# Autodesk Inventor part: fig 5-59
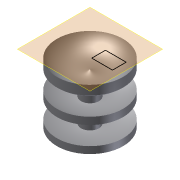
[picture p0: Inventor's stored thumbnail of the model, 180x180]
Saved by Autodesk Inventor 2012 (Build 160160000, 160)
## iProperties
Created: 2004-05
Part Number: fig 5-59
Document SubType Name: Modeling
Designer: CADCIM Technologies
Manufacturer: Standard
Standards Organization: Custom
Density: 1 g/cm^3
Material: Default
Author: CADCIM Technologies
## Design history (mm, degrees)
sketch "Sketch1"
  geometry: L1 (0.098, 22.743)-(0.098, 0.516); L2 (-3.621, 19.305)-(-3.621, 13.061); L3 (-3.621, 10.379)-(-3.621, 3.25); L4 (-3.664, 0.516)-(0.098, 0.516); L5 (-13.694, 4.7)-(-13.694, 1.836); L6 (-13.694, 26.851)-(-13.694, 23.014); L7 (-13.694, 15.335)-(-13.694, 12.343); A1 r 10.546 centre (-4.597, 32.185) between (-13.694, 26.851) and (0.098, 22.743); A2 r 21.828 centre (-4.597, 32.185) between (-13.694, 12.343) and (-3.621, 10.379); A3 r 12.918 centre (-4.597, 32.185) between (-13.694, 23.014) and (-3.621, 19.305); A4 r 19.149 centre (-4.597, 32.185) between (-13.694, 15.335) and (-3.621, 13.061); A5 r 28.952 centre (-4.597, 32.185) between (-13.694, 4.7) and (-3.621, 3.25); A6 r 31.683 centre (-4.597, 32.185) between (-13.694, 1.836) and (-3.664, 0.516)
  constraints: 14 end point, 12 point on circle, 6 centre point, 4 perpendicular, 2 parallel, 1 vertical
revolve "Revolution1" sketch "Sketch1" stored, may be unused: angle "d0" = 90 deg
workplane "Work Plane1"
sketch "Sketch2"
  geometry: L1 (3.408, -2.846)-(12.06, -2.846); L2 (12.06, -2.846)-(12.06, 2.873); L3 (12.06, 2.873)-(3.408, 2.873); L4 (3.408, 2.873)-(3.408, -2.846)
  constraints: 8 end point, 2 parallel, 1 horizontal, 1 perpendicular
body "Solid1"
